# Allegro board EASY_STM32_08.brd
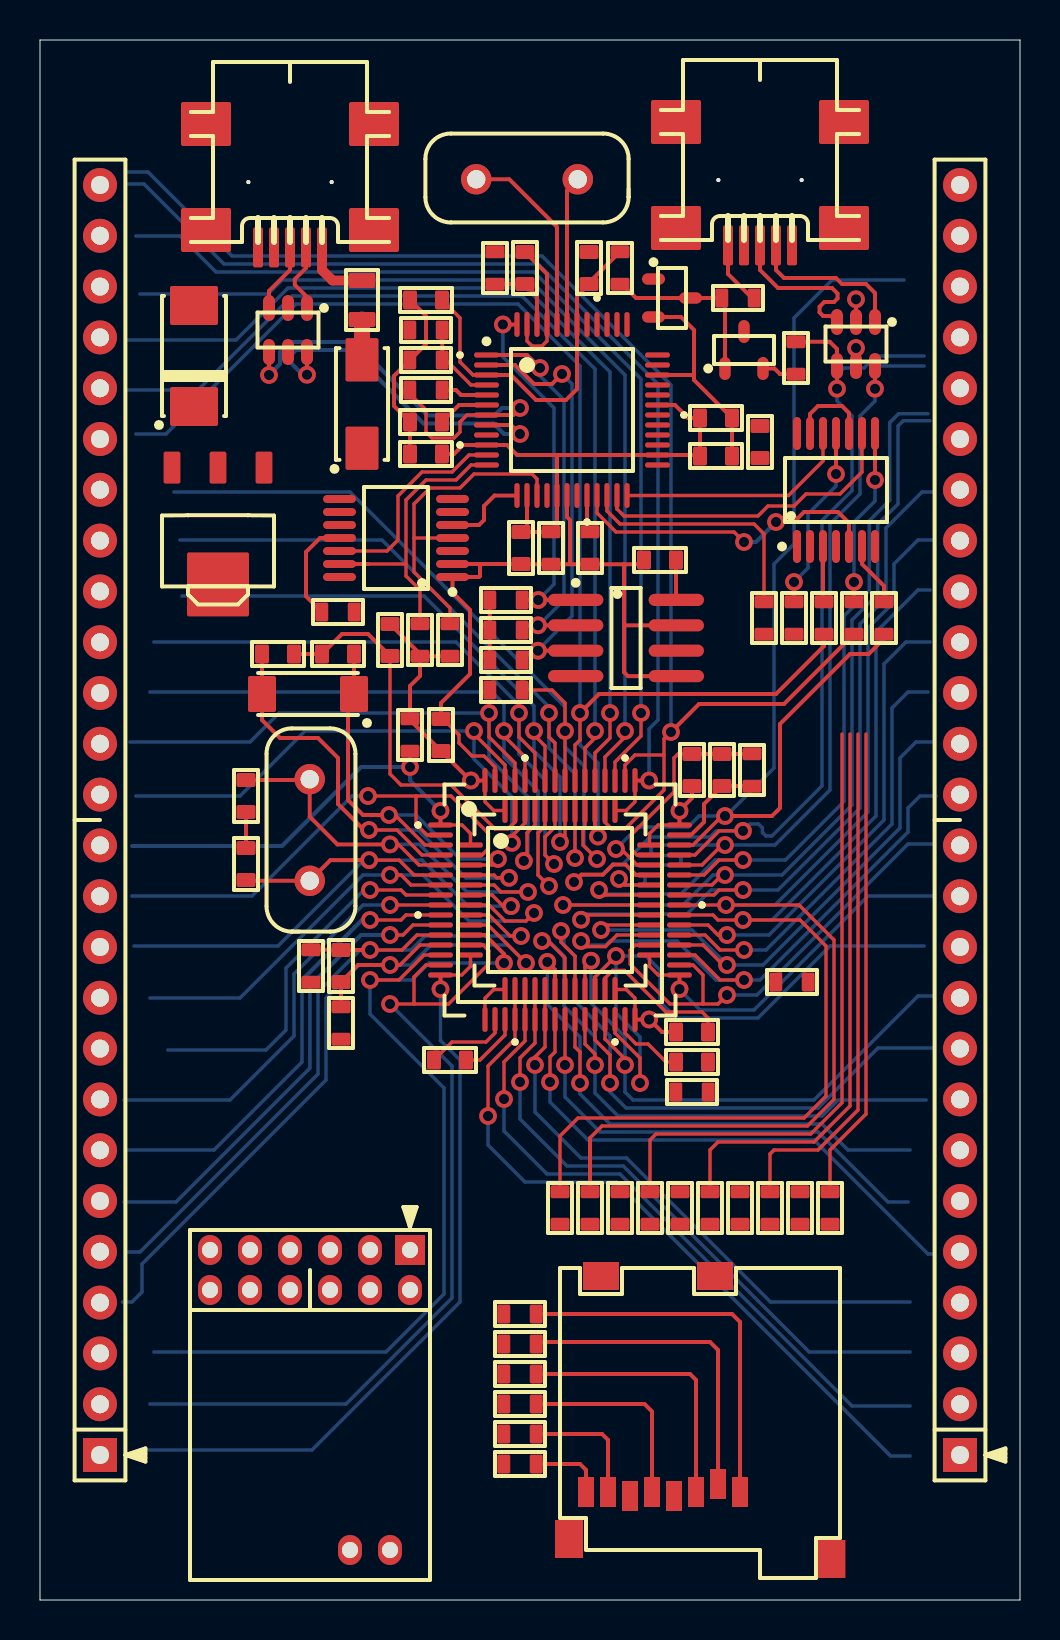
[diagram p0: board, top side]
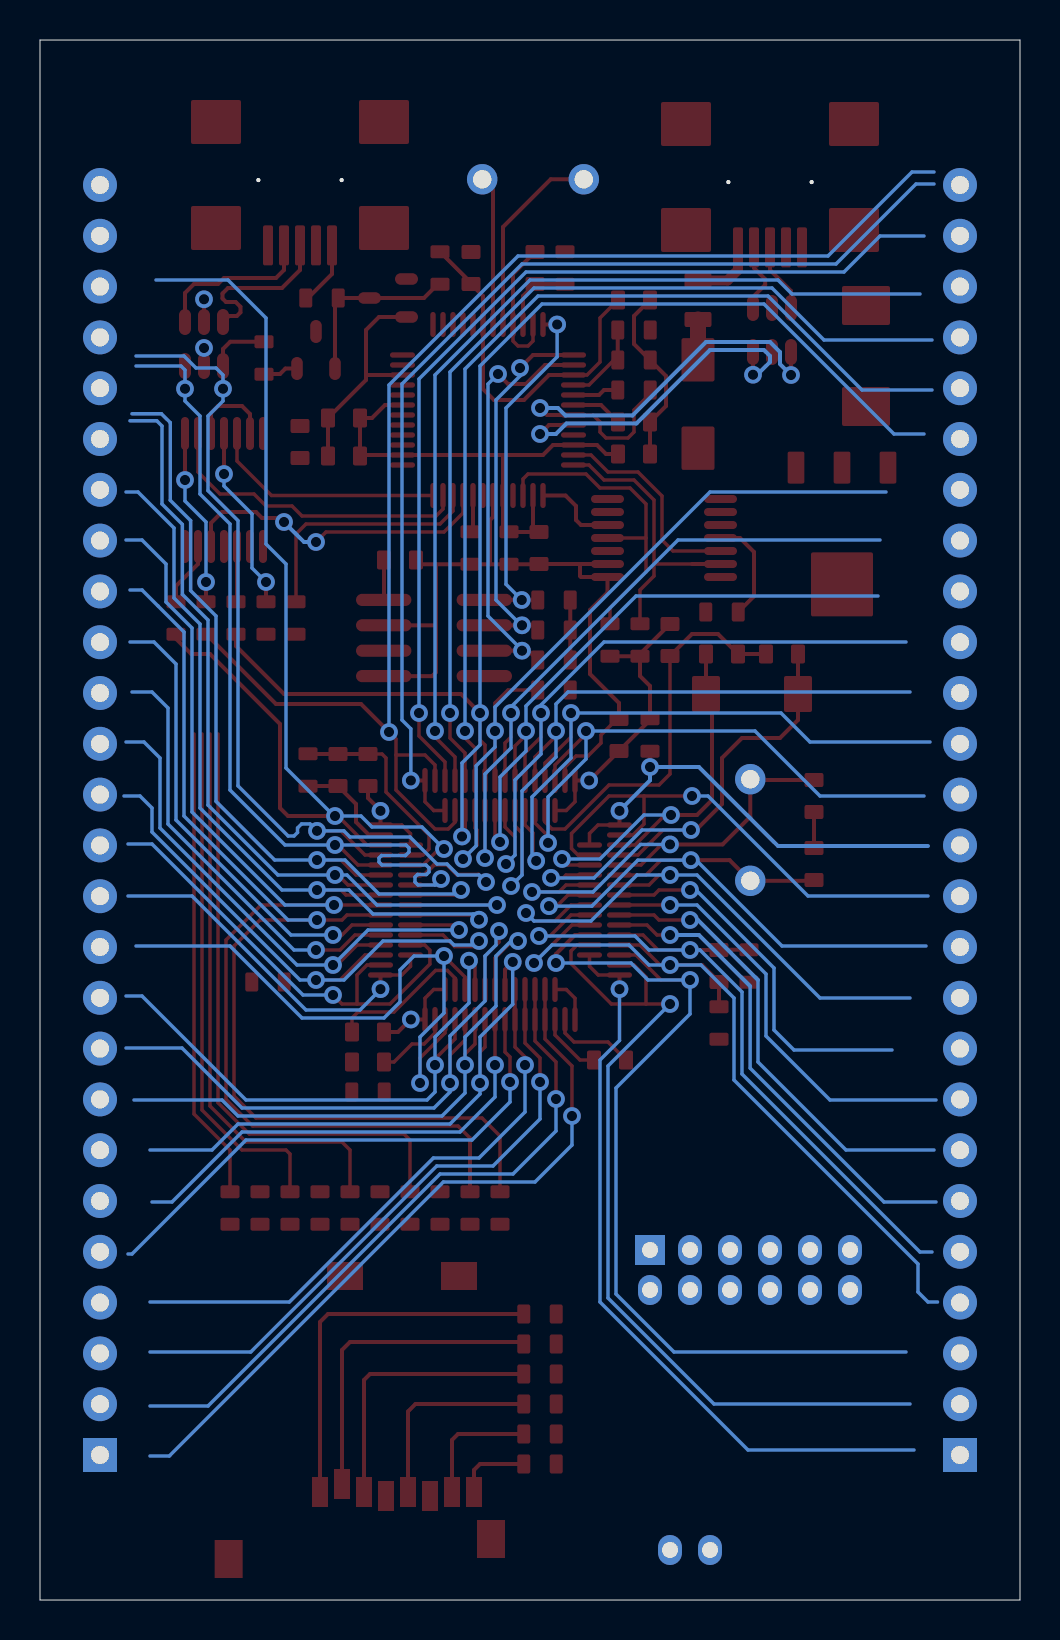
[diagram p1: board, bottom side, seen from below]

Outline 49 x 78 mm; copper layers: TOP, BOTTOM. Coordinates in mm from the lower left corner of the outline.
Outline path: 0,78 0,0 49,0 49,78 0,78

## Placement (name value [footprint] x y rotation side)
C1  22pF  [CAP0603_B]  10.3 40.2 270 top
C2  22p  [CAP0603_B]  10.3 36.8 90 top
C3  15p  [CAP0603_B]  11.9 47.3 0 top
C4  15p  [CAP0603_B]  14.9 47.3 180 top
C5  100n  [CAP0603_B]  15.05 31.7 90 top
C6  100n  [CAP0603_B]  32.6 28.4 0 top
C7  100n  [CAP0603_B]  32.6 41.5 90 top
C8  100n  [CAP0603_B]  20.05 43.25 90 top
C9  100n  [CAP0603_B]  20.5 27 180 top
C11  100n  [CAP0603_B]  19.3 65 180 top
C12  100n  [CAP0603_B]  27.45 66.6 90 top
C14  100n  [CAP0603_B]  19.3 57.3 180 top
C15  100n  [CAP0603_B]  24.05 52.6 270 top
C16  100n  [CAP0603_B]  33.8 57.2 0 top
C17  100n  [CAP0603_B]  33.8 59.1 0 top
C18  100n  [CAP0603_B]  24.25 66.6 90 top
C19  100n  [CAP0603_B]  19.3 58.9 180 top
C22  100n  [CAP0603_B]  31 52 180 top
C23  220uF  [CAP220UF]  7.7 62.2 90 top
C27  100n  [CAP0603_B]  32.6 26.9 0 top
C28  100n  [CAP0603_B]  34.1 41.5 90 top
C45  100nF  [CAP0603_B]  36 57.9 90 top
C46  100nF  [CAP0603_B]  17.5 48 270 top
D2  1N5819  [SS14]  16.1 59.8 90 top
J1  USB_MB  [HIROSE-US60-MB-5ST]  12.5 76.9 180 top
J2  USB_MB  [HIROSE-US60-MB-5ST]  36 77 180 top
J3  CON26  [HEADER26-1X26]  46 7.25 90 top
J4  CON26  [HEADER26-1X26]  3 7.25 90 top
L1  FB60R  [RES0805_B]  16.1 65 90 top
NOREF  -  [#2]  0 -2 0 top
NOREF#2  -  [#2]  50 0 90 top
Q1  C1815  [SOT-23]  35.2 62.5 0 top
Q2  C1815  [SOT-23]  31.6 65.1 270 top
R1  0R  [RES0603_B]  18.5 43.25 90 top
R2  0R  [RES0603_B]  15.05 28.85 270 top
R3  0R  [RES0603_B]  13.55 31.7 270 top
R4  470R  [RES0603_B]  22.75 66.6 270 top
R5  4K7  [RES0603_B]  19.3 63.5 0 top
R6  10K  [RES0603_B]  19.3 62 180 top
R7  10K  [RES0603_B]  27.5 52.6 270 top
R8  10K  [RES0603_B]  23.3 47 0 top
R9  10K  [RES0603_B]  23.3 48.5 0 top
R10  10K  [RES0603_B]  23.3 50 0 top
R13  1K5  [RES0603_B]  19.3 60.5 0 top
R14  100K  [RES0603_B]  25.55 52.6 270 top
R15  10K  [RES0603_B]  24 8.3 0 top
R16  10K  [RES0603_B]  24 11.3 0 top
R17  10K  [RES0603_B]  24 9.8 0 top
R18  10K  [RES0603_B]  24 12.8 0 top
R19  10K  [RES0603_B]  24 6.8 0 top
R20  10K  [RES0603_B]  24 14.3 0 top
R23  0R  [RES0603_B]  26 19.6 270 top
R24  0R  [RES0603_B]  33.5 19.6 270 top
R25  0R  [RES0603_B]  30.5 19.6 270 top
R26  0R  [RES0603_B]  36.5 19.6 270 top
R27  0R  [RES0603_B]  27.5 19.6 270 top
R28  0R  [RES0603_B]  39.5 19.6 270 top
R29  0R (DNP)  [RES0603_B]  29 19.6 90 top
R30  0R (DNP)  [RES0603_B]  35 19.6 90 top
R31  0R (DNP)  [RES0603_B]  32 19.6 90 top
R32  0R (DNP)  [RES0603_B]  38 19.6 90 top
R34  100K  [RES0603_B]  36.2 49.1 270 top
R35  100R  [RES0603_B]  39.2 49.1 270 top
R36  100R  [RES0603_B]  42.2 49.1 270 top
R37  100R  [RES0603_B]  40.7 49.1 270 top
R38  100R  [RES0603_B]  37.7 49.1 270 top
R39  100K  [RES0603_B]  19 48 90 top
R40  100K  [RES0603_B]  20.5 48 90 top
R41  100R  [RES0603_B]  23.3 45.5 0 top
R42  100R  [RES0603_B]  14.9 49.4 0 top
R43  0R  [RES0603_B]  32.6 25.4 0 top
R44  10K  [RES0603_B]  29 66.6 270 top
R45  36K  [RES0603_B]  34.9 65.1 0 top
R46  1K5  [RES0603_B]  37.8 62.1 90 top
R47  47K  [RES0603_B]  37.6 30.9 0 top
R48  0R  [RES0603_B]  35.6 41.5 90 top
REF  val  [unnamed]  18.5 17.5 180 top
U1  STM32F103RCT6  [LQFP64_MODIFIED]  26 35 0 top
U2  STM32F100  [LQFP48L_MODIFIED]  26 35 0 top
U3  FT2232D  [LQFP48L]  26.6 59.5 0 top
U4  AT93C46-10SI-2.7  [SOIC8S1JEDECM]  29.3 48.1 270 top
U5  74LVC125A  [TSOP65P640X120-14]  39.8 55.5 0 top
U6  74LVC125A  [TSOP65P640X120-14]  17.8 53.1 90 top
U7  LD1117-3V3  [SOT-223]  8.9 53.42 180 top
U10  MICRO_SD  [MICRO_SD_PUSH]  40 16.6 180 top
U11  USBLC6-2P6  [SOT23-6L]  40.8 62.8 180 top
U12  USBLC6-2P6  [SOT23-6L]  12.4 63.5 180 top
Y1  8M  [XTAL_DIP]  13.49 35.96 90 top
Y2  32.768KHz  [ABS10]  13.4 45.3 180 top
Y3  6M  [XTAL_DIP]  26.89 71.04 180 top

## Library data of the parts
C1-C9 C27 C28 = C1005_0: User Part Number: pn; Tolerance: RichardLC
C11 C12 C14-C19 C22 = CAP NP_0: User Part Number: pn; Tolerance: RichardLC
C23 = CAPACITOR POL: User Part Number: pn; Tolerance: RichardLC
C45 C46 = C1005_5: User Part Number: pn; Tolerance: RichardLC
D2 = DIODE SCHOTTKY_1: User Part Number: pn; Tolerance: RichardLC
J1 J2 = CON9_2: User Part Number: pn; Tolerance: RichardLC
J3 J4 = CON26: User Part Number: pn; Tolerance: RichardLC
L1 = INDUCTOR/SM_0: User Part Number: pn; Tolerance: RichardLC
Q1 Q2 = 2N3904_0: User Part Number: pn; Tolerance: RichardLC
R1-R10 R13-R20 R23-R32 R34-R48 = R_0: User Part Number: pn; Tolerance: RichardLC
REF = -: User Part Number: pn; Tolerance: RichardLC
U1 = STM32F103RCT6_2: User Part Number: pn; Tolerance: RichardLC
U2 = STM32F100_1: User Part Number: pn; Tolerance: RichardLC
U3 = FT2232D_0: User Part Number: pn; Tolerance: RichardLC
U4 = 93C46_2: User Part Number: pn; Tolerance: RichardLC
U5 U6 = 74HC125/LCC_0: User Part Number: pn; Tolerance: RichardLC
U7 = LD1117: User Part Number: pn; Tolerance: RichardLC
U10 = MOLEX_uSD_0: User Part Number: pn; Tolerance: RichardLC
U11 U12 = USBLC6-2P6: User Part Number: pn; Tolerance: RichardLC
Y1 Y3 = ZTB: Tolerance: ***; User Part Number: ***
Y2 = ZTA: User Part Number: pn; Tolerance: RichardLC

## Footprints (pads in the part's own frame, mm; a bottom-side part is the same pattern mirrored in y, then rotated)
ABS10
  custom 0.35x0.35 smd: 1(-2.3,0) 2(2.3,0)
CAP220UF
  custom 0.487x0.487 smd: 1(-2.525,0) 2(2.525,0)
CAP0603_B
  custom 0.175x0.175 smd: 1(-0.8,0) 2(0.8,0)
HEADER26-1X26
  rect 1.7x1.7 hole 0.9: 1(0,0)
  round 1.7 hole 0.9: 2(2.54,0) 3(5.08,0) 4(7.62,0) 5(10.16,0) 6(12.7,0) 7(15.24,0) 8(17.78,0) 9(20.32,0) 10(22.86,0) 11(25.4,0) 12(27.94,0) 13(30.48,0) 14(33.02,0) 15(35.56,0) 16(38.1,0) 17(40.64,0) 18(43.18,0) 19(45.72,0) 20(48.26,0) 21(50.8,0) 22(53.34,0) 23(55.88,0) 24(58.42,0) 25(60.96,0) 26(63.5,0)
HIROSE-US60-MB-5ST
  round 0.2 hole 0.9 unplated: (-2.083,6.005) (2.083,6.005)
  custom 0.125x0.125 smd: 1(-1.6,9.271) 2(-0.8,9.271) 3(0,9.271) 4(0.8,9.271) 5(1.6,9.271)
  custom 0.55x0.55 smd: 6(-4.2,3.1) 7(4.2,3.1) 8(-4.2,8.4) 9(4.2,8.4)
LQFP48L
  oval 1.25x0.27 smd: 1(-4.275,2.75) 2(-4.275,2.25) 3(-4.275,1.75) 4(-4.275,1.25) 5(-4.275,0.75) 6(-4.275,0.25) 7(-4.275,-0.25) 8(-4.275,-0.75) 9(-4.275,-1.25) 10(-4.275,-1.75) 11(-4.275,-2.25) 12(-4.275,-2.75) 25(4.275,-2.75) 26(4.275,-2.25) 27(4.275,-1.75) 28(4.275,-1.25) 29(4.275,-0.75) 30(4.275,-0.25) 31(4.275,0.25) 32(4.275,0.75) 33(4.275,1.25) 34(4.275,1.75) 35(4.275,2.25) 36(4.275,2.75)
  oval 0.27x1.25 smd: 13(-2.75,-4.275) 14(-2.25,-4.275) 15(-1.75,-4.275) 16(-1.25,-4.275) 17(-0.75,-4.275) 18(-0.25,-4.275) 19(0.25,-4.275) 20(0.75,-4.275) 21(1.25,-4.275) 22(1.75,-4.275) 23(2.25,-4.275) 24(2.75,-4.275) 37(2.75,4.275) 38(2.25,4.275) 39(1.75,4.275) 40(1.25,4.275) 41(0.75,4.275) 42(0.25,4.275) 43(-0.25,4.275) 44(-0.75,4.275) 45(-1.25,4.275) 46(-1.75,4.275) 47(-2.25,4.275) 48(-2.75,4.275)
LQFP48L_MODIFIED
  oval 1.25x0.27 smd: 1(-4.475,2.75) 2(-4.475,2.25) 3(-4.475,1.75) 4(-4.475,1.25) 5(-4.475,0.75) 6(-4.475,0.25) 7(-4.475,-0.25) 8(-4.475,-0.75) 9(-4.475,-1.25) 10(-4.475,-1.75) 11(-4.475,-2.25) 12(-4.475,-2.75) 25(4.475,-2.75) 26(4.475,-2.25) 27(4.475,-1.75) 28(4.475,-1.25) 29(4.475,-0.75) 30(4.475,-0.25) 31(4.475,0.25) 32(4.475,0.75) 33(4.475,1.25) 34(4.475,1.75) 35(4.475,2.25) 36(4.475,2.75)
  oval 0.27x1.25 smd: 13(-2.75,-4.475) 14(-2.25,-4.475) 15(-1.75,-4.475) 16(-1.25,-4.475) 17(-0.75,-4.475) 18(-0.25,-4.475) 19(0.25,-4.475) 20(0.75,-4.475) 21(1.25,-4.475) 22(1.75,-4.475) 23(2.25,-4.475) 24(2.75,-4.475) 37(2.75,4.475) 38(2.25,4.475) 39(1.75,4.475) 40(1.25,4.475) 41(0.75,4.475) 42(0.25,4.475) 43(-0.25,4.475) 44(-0.75,4.475) 45(-1.25,4.475) 46(-1.75,4.475) 47(-2.25,4.475) 48(-2.75,4.475)
LQFP64_MODIFIED
  oval 1.25x0.27 smd: 1(-5.975,3.75) 2(-5.975,3.25) 3(-5.975,2.75) 4(-5.975,2.25) 5(-5.975,1.75) 6(-5.975,1.25) 7(-5.975,0.75) 8(-5.975,0.25) 9(-5.975,-0.25) 10(-5.975,-0.75) 11(-5.975,-1.25) 12(-5.975,-1.75) 13(-5.975,-2.25) 14(-5.975,-2.75) 15(-5.975,-3.25) 16(-5.975,-3.75) 33(5.975,-3.75) 34(5.975,-3.25) 35(5.975,-2.75) 36(5.975,-2.25) 37(5.975,-1.75) 38(5.975,-1.25) 39(5.975,-0.75) 40(5.975,-0.25) 41(5.975,0.25) 42(5.975,0.75) 43(5.975,1.25) 44(5.975,1.75) 45(5.975,2.25) 46(5.975,2.75) 47(5.975,3.25) 48(5.975,3.75)
  oval 0.27x1.25 smd: 17(-3.75,-5.975) 18(-3.25,-5.975) 19(-2.75,-5.975) 20(-2.25,-5.975) 21(-1.75,-5.975) 22(-1.25,-5.975) 23(-0.75,-5.975) 24(-0.25,-5.975) 25(0.25,-5.975) 26(0.75,-5.975) 27(1.25,-5.975) 28(1.75,-5.975) 29(2.25,-5.975) 30(2.75,-5.975) 31(3.25,-5.975) 32(3.75,-5.975) 49(3.75,5.975) 50(3.25,5.975) 51(2.75,5.975) 52(2.25,5.975) 53(1.75,5.975) 54(1.25,5.975) 55(0.75,5.975) 56(0.25,5.975) 57(-0.25,5.975) 58(-0.75,5.975) 59(-1.25,5.975) 60(-1.75,5.975) 61(-2.25,5.975) 62(-2.75,5.975) 63(-3.25,5.975) 64(-3.75,5.975)
MICRO_SD_PUSH
  rect 0.8x1.5 smd: 1(5,11.2) 2(6.1,10.8) 3(7.2,11.2) 4(8.3,11.4) 5(9.4,11.2) 6(10.5,11.4) 7(11.6,11.2) 8(12.7,11.2)
  rect 1.4x1.9 smd: G1(0.43,14.55) G2(13.55,13.55)
  rect 1.8x1.4 smd: S1(6.25,0.4) S2(11.95,0.4)
RES0603_B
  custom 0.163x0.163 smd: 1(-0.812,0) 2(0.812,0)
RES0805_B
  custom 0.188x0.188 smd: 1(-0.975,0) 2(0.975,0)
SOIC8S1JEDECM
  oval 0.61x2.77 smd: 1(-1.905,-2.515) 2(-0.635,-2.515) 3(0.635,-2.515) 4(1.905,-2.515) 5(1.905,2.515) 6(0.635,2.515) 7(-0.635,2.515) 8(-1.905,2.515)
SOT23-6L
  oval 0.6x1.3 smd: 1(-0.95,-1.1) 2(0,-1.1) 3(0.95,-1.1) 4(0.95,1.1) 5(0,1.1) 6(-0.95,1.1)
SOT-23
  oval 0.58x1.15 smd: 1(-0.95,-0.925) 2(0.95,-0.925) 3(0,0.925)
SOT-223
  custom 0.21x0.21 smd: 1(-2.3,-3.195) 2(0,-3.195) 3(2.3,-3.195)
  custom 0.775x0.775 smd: 4(0,2.645)
SS14
  custom 0.412x0.412 smd: A(2.21,0) C(-2.21,0)
TSOP65P640X120-14
  oval 0.4x1.65 smd: 1(-1.95,-2.825) 2(-1.3,-2.825) 3(-0.65,-2.825) 4(0,-2.825) 5(0.65,-2.825) 6(1.3,-2.825) 7(1.95,-2.825) 8(1.95,2.825) 9(1.3,2.825) 10(0.65,2.825) 11(0,2.825) 12(-0.65,2.825) 13(-1.3,2.825) 14(-1.95,2.825)
unnamed
  rect 1.5x1.5 hole 0.8: 1(0,0)
  oval 1.194x1.499 hole 0.8: 2(0,2) 3(2,0) 4(2,2) 5(4,0) 6(4,2) 7(6,0) 8(6,2) 9(8,0) 10(8,2) 11(10,0) 12(10,2) 13(1,15) 14(3,15)
XTAL_DIP
  round 1.524 hole 0.914: 1(0,0) 2(5.08,0)

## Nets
+3V3: C6.1 C7.1 C8.1 C9.1 C14.1 C15.1 C16.1 C17.1 C45.1 C46.1 Q1.3(C) R1.2 R2.2 R14.1 R15.1 R16.1 R17.1 R18.1 R19.1 R20.1 R39.1 R40.1 R47.1 U1.19(VDD_4) U1.32(VDD_1) U1.48(VDD_2) U1.64(VDD_3) U2.24(VDD_1) U2.36(VDD_2) U2.48(VDD_3) U3.10(SI/WUA) U3.14(VCCIOA) U3.17(ADBUS6) U3.26(SI/WUB) U3.31(VCCIOB) U5.14(VCC) U6.14(VCC) U7.2(VOUT) U7.4(SH) U10.4(VDD)
+5V: C11.1 C12.1 C22.1 C23.1 D2.C R4.1 R8.1 R9.1 R10.1 R44.1 U3.3(VCC1) U3.42(VCC2) U4.8(VCC) U7.3(VIN) U11.5(VBUS) U12.5(VBUS)
GND: C1.2 C2.2 C3.2 C4.2 C6.2 C7.2 C8.2 C9.2 C11.2 C12.2 C14.2 C15.2 C16.2 C17.2 C18.2 C19.2 C22.2 C23.2 C27.2 C28.2 C45.2 C46.2 J1.5(GND) J1.6(SH1) J1.7(SH2) J1.8(SH3) J1.9(SH4) J2.5(GND) J2.6(SH1) J2.7(SH2) J2.8(SH3) J2.9(SH4) Q2.2(E) R3.2 R6.2 R7.2 R14.2 R34.2 R43.2 R45.2 R48.2 U1.18(VSS_4) U1.63(VSS_3) U2.23(VSS_1) U2.35(VSS_2) U2.47(VSS_3) U3.9(GND1) U3.18(GND2) U3.25(GND3) U3.34(GND4) U3.45(AGND) U3.47(TEST) U4.5(GND) U4.7(NC) U5.7(GND) U6.1(O\E\1\) U6.2(A1) U6.7(GND) U6.9(A3) U6.10(O\E\3\) U7.1(GND) U10.6(VSS) U11.2(GND) U12.2(GND)
VBAT: R1.1 U1.1(VBAT) U2.1(VBAT)
VDDA: C5.1 R2.1 U1.13(VDDA) U2.9(VDDA)
VSSA: C5.2 R3.1 U1.12(VSSA) U2.8(VSSA)
BOOT0: U1.60(BOOT0) U2.44(BOOT0)
EECK: R9.2 U3.1(EESK) U4.2(CLK)
EECS: R10.2 U3.48(EECS) U4.1(CS)
EEDA: R8.2 U3.2(EEDATA) U4.3(DI)
JT_SRSTN: U3.16(ADBUS7)
JTG_SELN: U5.1(O\E\1\) U5.4(O\E\2\) U5.10(O\E\3\) U5.13(O\E\4\)
NRST: R42.2 U1.7(NRST) U2.7(NRST)
OSC32_IN: C4.1 U1.3(PC14/OSC32_IN) U2.3(PC14/OSC32_IN) Y2.1
OSC32_OUT: C3.1 U1.4(PC15/OSC32/OUT) U2.4(PC15/OSC32_OUT) Y2.2
OSC_IN: C1.1 U1.5(PD0/OSC_IN) U2.5(PD0/OSC_IN) Y1.2
OSC_OUT: C2.1 U1.6(PD1/OSC_OUT) U2.6(PD1/OSC_OUT) Y1.1
PA0: U1.14(PA0-WKUP) U2.10(PA0/WKUP)
PA1: U1.15(PA1) U2.11(PA1)
PA2: U1.16(PA2) U2.12(PA2)
PA3: U1.17(PA3) U2.13(PA3)
PA4: R32.2 U1.20(PA4) U2.14(PA4)
PA5: R31.2 U1.21(PA5) U2.15(PA5)
PA6: R29.2 U1.22(PA6) U2.16(PA6)
PA7: R30.2 U1.23(PA7) U2.17(PA7)
PA8: U1.41(PA8) U2.29(PA8)
PA9: U1.42(PA9) U2.30(PA9)
PA10: U1.43(PA10) U2.31(PA10)
PA11: U1.44(PA11) U2.32(PA11) U11.6(IO1_2)
PA12: R46.2 U1.45(PA12) U2.33(PA12) U11.4(IO2_2)
PA13: R36.2 U1.46(PA13) U2.34(PA13)
PA14: R38.2 U1.49(PA14) U2.37(PA14)
PA15: R37.2 U1.50(PA15) U2.38(PA15)
PB0: U1.26(PB0) U2.18(PB0)
PB1: U1.27(PB1) U2.19(PB1)
PB2: U1.28(PB2/BOOT1) U2.20(PB2)
PB3: R35.2 U1.55(PB3) U2.39(PB3)
PB4: R41.2 U1.56(PB4) U2.40(PB4)
PB5: U1.57(PB5) U2.41(PB5)
PB6: U1.58(PB6) U2.42(PB6)
PB7: U1.59(PB7) U2.43(PB7)
PB8: U1.61(PB8) U2.45(PB8)
PB9: U1.62(PB9) U2.46(PB9)
PB10: U1.29(PB10) U2.21(PB10)
PB11: U1.30(PB11) U2.22(PB11)
PB12: U1.33(PB12) U2.25(PB12)
PB13: U1.34(PB13) U2.26(PB13)
PB14: Q2.1(B) R47.2 U1.35(PB14) U2.27(PB14)
PB15: U1.36(PB15) U2.28(PB15)
PC0: U1.8(PC0)
PC1: U1.9(PC1)
PC2: U1.10(PC2)
PC3: U1.11(PC3)
PC4: U1.24(PC4)
PC5: U1.25(PC5)
PC6: U1.37(PC6)
PC7: U1.38(PC7)
PC8: R23.1 U1.39(PC8)
PC9: R27.1 U1.40(PC9)
PC10: R28.1 U1.51(PC10)
PC11: R26.1 U1.52(PC11)
PC12: R25.1 U1.53(PC12)
PC13: U1.2(PC13/TAMPER/RTC) U2.2(PC13/TAMPER/RTC)
PD2: R24.1 U1.54(PD2)
RXD: U3.39(BDBUS1)
SRST: U3.11(ACBUS3) U6.12(A4)
SRST_OE: R39.2 U3.12(ACBUS2) U6.13(O\E\4\)
TRST: U3.13(ACBUS1) U6.5(A2)
TRST_OE: R40.2 U3.15(ACBUS0) U6.4(O\E\2\)
TXD: U3.40(BDBUS0)
USB_CLK: U3.24(ADBUS0) U5.12(A4)
USB_TDI: U3.23(ADBUS1) U5.9(A3)
USB_TDO: R34.1 U3.22(ADBUS2) U5.2(A1)
USB_TMS: U3.21(ADBUS3) U5.5(A2)
N50123: R13.1 U3.7(USBDP) U12.4(IO2_2)
N50127: C18.1 R4.2 U3.46(AVCC)
N50535: R7.1 U3.20(ADBUS4)
N50793: U3.43(XTIN) Y3.1
N50801: U3.44(XTOUT) Y3.2
N51029: D2.A L1.1 R5.1
N51243: J1.1(VBUS) L1.2
N51319: R13.2 U3.5(R\S\T\O\U\T\)
N51343: U3.8(USBDM) U12.6(IO1_2)
N51347: R5.2 R6.1 U3.4(R\E\S\E\T\)
N51363: C19.1 U3.6(3V3OUT)
N51511: U4.4(DO)
N70187: R15.2 R23.2 R29.1 U10.7(DAT0/DO)
N70219: R17.2 R25.2 R31.1 U10.5(CLK)
N70227: R18.2 R26.2 R32.1 U10.2(CD/C\S\/DAT3)
N70305: U10.S2
N70345: U10.G2
N70603: R19.2 R27.2 U10.8(DAT1/RSV)
N14914218: R16.2 R24.2 R30.1 U10.3(CMD/DI)
N14919452: R35.1 U5.3(Y1)
N14919456: R36.1 U5.6(Y2)
N14919460: R37.1 U5.8(Y3)
N14919464: R38.1 U5.11(Y4)
N14919761: R20.2 R28.2 U10.1(DAT2/NC)
N14928576: R41.1 U6.6(Y2)
N14928580: R42.1 U6.11(Y4)
N14948550: J2.1(VBUS)
N14948554: J2.2(DM) U11.1(IO1_1)
N14948558: J2.3(DP) U11.3(IO2_1)
N14952468: Q1.2(E) R46.1
N14953185: Q1.1(B) Q2.3(C) R44.2 R45.1
N14959571: J1.3(DP) U12.3(IO2_1)
N14961045: J1.2(DM) U12.1(IO1_1)
N14964930: C27.1 R43.1 U1.31(VSS_1)
N14964937: C28.1 R48.1 U1.47(VSS_2)

Pads without a net: J1 4; J2 4; J3 1 2 3 4 5 6 7 8 9 10 11 12 13 14 15 16 17 18 19 20 21 22 23 24 25 26; J4 1 2 3 4 5 6 7 8 9 10 11 12 13 14 15 16 17 18 19 20 21 22 23 24 25 26; REF 1 2 3 4 5 6 7 8 9 10 11 12 13 14; U3 19 27 28 29 30 32 33 35 36 37 38 41; U4 6; U6 3 8; U10 G1 S1

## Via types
v1: diameter 0.889, hole 0.508, TOP to BOTTOM, 108 vias

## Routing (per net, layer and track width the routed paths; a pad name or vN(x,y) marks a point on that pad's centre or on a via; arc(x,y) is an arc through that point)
+3V3: length 51.7
  TOP w0.175: U1.64 22.25,39.91 22.69,39.48 U2.48 ; U2.24 29.32,30.52 29.57,30.27 29.75,30.09 U1.32 ; C9.1 22,27 23.25,28.25 U1.19 ; U2.36 30.48,38.31 30.91,38.75 U1.48
  TOP w0.2: U3.31 31.75,59.75 32.4,59.1 C17.1 C16.1 32.95,57.25 U3.26 25.8,57.25 ; U1.32 v1(30.46,29.02) 30.48,29.02 31.1,28.4 C6.1 ; 25.8,57.25 23.85,57.25 23.35,57.75 U3.10 21.15,57.75 20.7,57.3 C14.1 ; 25.8,57.25 25.85,57.2 U3.17 25.85,53.71 R14.1 25.54,53.4 C15.1 24.35,53.7 U3.14 ; R39.1 19,47.3 C46.1 ; R39.1 R40.1 ; R39.1 19,46.2 18.5,45.7 R1.2 18.5,44 C8.1 21.52,40.98 v1(21.54,40.98) U1.64 ; C7.1 32.6,40.1 31.98,39.48 v1(31.98,39.46) U1.48
+5V: length 24
  TOP w0.175: C11.1 21,64.1 21,61.9 21.65,61.25 U3.3
  TOP w0.2: 31.82,50.01 31.8,50.02 C22.1 ; U11.5 v1(40.8,62.6) ; R44.1 27.45,65.86 C12.1 26.85,65.2 U3.42 26.85,60.55 26.3,60 24.8,60 23.55,61.25 U3.3 ; R8.1 R9.1 R10.1
GND: length 113.9
  TOP w0.175: U1.63 22.75,41.65 22.2,42.2 21.6,42.2 20.95,42.85 20.95,43.25 20.15,44.05 C8.2 ; U2.47 23.75,38.9 23.4,38.55 22.75,38.55 20.55,40.75 18.05,40.75 17.5,41.3 C46.2 ; C7.2 31.9,42.3 31.7,42.1 31.7,40.4 29.55,38.25 29.55,37.55 29.85,37.25 U2.35 ; C9.2 20.6,27.9 22.3,27.9 22.75,28.35 U1.18 ; U3.47 24.35,62.95 24.6,62.7 25.1,62.7 25.35,62.95 U3.45 ; C6.2 33.4,29.1 33.1,29.4 31.3,29.4 29.22,31.48 28.63,31.48 28.25,31.09 U2.23
  TOP w0.2: C3.2 C4.2 15.1,48.3 16.4,48.3 C46.2 ; C8.2 20.05,44.85 21.5,46.3 21.5,49.5 20.62,50.38 20.62,51.15 21.95,51.15 22,51.2 22,51.8 ; C2.2 C1.2 ; U11.2 v1(40.8,65.04) ; C14.2 C19.2 17.7,59.7 17.7,61.2 18.49,61.99 R6.2 18.5,62 19.3,62.8 19.3,64.2 C11.2 ; 29.2,51.79 R7.2 26.5,51.79 ; 29.2,51.79 29.2,48.7 ; 29.2,51.79 29.99,51.79 C22.2 ; R48.2 35.59,42.3 C28.2 C7.2 ; Q2.2 32.05,64.15 32.7,63.5 32.7,61.3 ; U3.18 26.35,54.15 26.5,54 26.5,51.79 ; 32.7,61.3 32.65,61.25 U3.34 ; 32.7,61.3 32.7,61 C17.2 C16.2 ; 31.82,46.2 29.39,46.2 29.2,46.39 29.2,48.7 ; 29.2,48.7 29.23,48.73 31.82,48.73 ; 22,51.8 C15.2 24.06,51.79 R14.2 26.5,51.79 ; 22,51.8 20.62,51.8 ; C18.2 25.35,66.3 U3.45 ; R45.2 35.6,65.1 34.4,66.3 J2.5
VBAT: length 22.1
  TOP w0.175: U1.1 21.1,38.75 21.52,38.33 U2.1
  TOP w0.2: R1.1 v1(18.5,41.65) ; U1.1 v1(20.02,39.46)
  BOTTOM w0.2: v1(20.02,39.46) 18.5,40.98 v1(18.5,41.65) 16.05,41.65 12.1,37.7 4.6,37.7
VDDA: length 41.7
  TOP w0.175: v1(24.3,31.85) 22.4,33.75 U2.9 ; U1.13 19,32.75 18,31.75 v1(17.5,31.75)
  TOP w0.2: R2.1 C5.1 15.9,31.75 v1(17.5,31.75)
  BOTTOM w0.175: 4.12,14.9 4.6,14.9 5.1,15.4 5.1,16.8 14.3,26 14.3,30.1 15.95,31.75 v1(17.5,31.75) 18.55,31.75 19.55,32.75 23.4,32.75 v1(24.3,31.85)
VSSA: length 38.3
  TOP w0.175: v1(16.5,32.5) 18.1,32.5 18.85,33.25 U1.12 ; U2.8 22.45,34.25 23.5,33.2 v1(24.05,33.2)
  TOP w0.2: R3.1 15.04,32.51 C5.2 v1(16.5,32.5)
  BOTTOM w0.175: 4.4,17.4 5,17.4 13.9,26.3 13.9,30.4 16,32.5 v1(16.5,32.5) 18.55,32.5 19.25,33.2 v1(24.05,33.2)
BOOT0: length 35
  TOP w0.175: v1(23.2,43.45) 23.2,43.2 24.25,42.15 U1.60 ; U2.44 25.25,38.7 24.9,38.35 24.9,36.25 v1(25.45,35.7)
  BOTTOM w0.175: v1(25.45,35.7) 24.9,36.25 24.9,40.45 23.2,42.15 v1(23.2,43.45) 23.2,44.8 22.6,45.4 5.5,45.4
EECK: length 19.6
  TOP w0.2: U3.1 24.35,62.25 v1(25,61.6) ; U4.2 v1(24.9,48.73) 24.35,48.73 R9.2
  BOTTOM w0.175: v1(25,61.6) 25,61.2 26.2,60 26.2,50 24.93,48.73 v1(24.9,48.73)
EECS: length 19.3
  TOP w0.2: v1(24.91,50) R10.2 24.12,50.01 U4.1 ; U3.48 v1(23.14,63.77)
  BOTTOM w0.175: v1(24.91,50) 25.7,50.79 25.7,59.6 23.14,62.16 v1(23.14,63.77)
EEDA: length 22
  TOP w0.2: U3.2 23.75,61.75 24.7,60.8 25.6,60.8 v1(26.1,61.3) ; R8.2 24.58,47.47 v1(24.9,47.47) U4.3
  BOTTOM w0.175: v1(24.9,47.47) 24.9,47.5 26.6,49.2 26.6,60.8 v1(26.1,61.3)
JTG_SELN: length 4.3
  TOP w0.2: U5.10 40.45,59.35 40.1,59.7 38.9,59.7 38.5,59.3 U5.13
NRST: length 29.3
  TOP w0.175: v1(17.5,36.25) 18.05,36.25 18.55,35.75 U1.7 ; U2.7 22.45,34.75 23.25,33.95 24.3,33.95 v1(24.7,34.35)
  BOTTOM w0.175: v1(24.7,34.35) 24.3,33.95 21.45,33.95 19.15,36.25 v1(17.5,36.25) 16.15,36.25 10,30.1 5.5,30.1
OSC32_IN: length 20.8
  TOP w0.175: v1(17.45,39.25) 17.75,39.25 19.25,37.75 U1.3 ; v1(22.9,37.05) 22.6,36.75 U2.3
  TOP w0.2: C4.1 Y2.1 15.4,45 15.4,40 16.15,39.25 v1(17.45,39.25)
  BOTTOM w0.175: v1(22.9,37.05) 21,37.05 18.8,39.25 v1(17.45,39.25)
OSC32_OUT: length 26.3
  TOP w0.175: v1(23.45,36.11) 22.84,36.11 22.7,36.25 U2.4 ; U1.4 19.1,37.25 17.85,38.5 v1(16.45,38.5)
  TOP w0.2: C3.1 Y2.2 11.1,44 12,43.1 13.9,43.1 14.9,42.1 14.9,39.8 16.2,38.5 v1(16.45,38.5)
  BOTTOM w0.175: v1(23.45,36.11) 23.44,36.1 21.3,36.1 18.9,38.5 v1(16.45,38.5)
OSC_IN: length 23.5
  TOP w0.175: v1(17.5,37.78) 17.92,37.78 18.95,36.75 U1.5 ; v1(24.4,35.4) 23.05,35.4 22.7,35.75 U2.5
  TOP w0.2: v1(17.5,37.78) 14.87,37.78 13.49,39.16 Y1.2 13.45,41 C1.1
  BOTTOM w0.175: v1(17.5,37.78) 18.97,37.78 21.35,35.4 v1(24.4,35.4)
OSC_OUT: length 34.3
  TOP w0.175: v1(23.55,34.69) 23.16,34.69 22.6,35.25 U2.6 ; U1.6 18.7,36.25 17.96,36.99 v1(16.46,36.99)
  TOP w0.2: C2.1 10.34,35.96 Y1.1 14.52,36.99 v1(16.46,36.99)
  BOTTOM w0.175: v1(23.55,34.69) 21.41,34.69 19.11,36.99 v1(16.46,36.99) 16.19,36.99 11.9,32.7 4.7,32.7
PA0: length 46.5
  TOP w0.175: v1(16.5,31) 17.95,31 19.2,32.25 U1.14
  TOP w0.2: v1(23.2,31.85) 23.2,32.3 22.25,33.25 U2.10
  BOTTOM w0.175: v1(23.2,31.85) 19.45,31.85 18.6,31 v1(16.5,31) 16.5,29.3 20.2,25.6 20.2,15.3 17.3,12.4 5.7,12.4
PA1: length 43.7
  TOP w0.175: 18.7,29.8 20.43,29.8 22.45,31.82 22.45,32.45 22.15,32.75 U2.11 ; 18.7,29.8 18.7,31.15 19.3,31.75 U1.15 ; 18.7,29.8 v1(17.5,29.8)
  BOTTOM w0.175: v1(17.5,29.8) 20.6,26.7 20.6,15.1 15.3,9.8 5.5,9.8
PA2: length 37.8
  TOP w0.175: U1.16 21.09,31.25 21.52,31.68 U2.12
  TOP w0.2: U1.16 v1(20.02,30.54)
  BOTTOM w0.175: 5.3,7.5 13.6,7.5 21,14.9 21,27 20.02,27.98 v1(20.02,30.54)
PA3: length 2.2
  TOP w0.175: U1.17 22.25,30.09 22.68,30.52 U2.13
PA4: length 36.1
  TOP w0.175: 23.75,30.73 U2.14 U1.20 23.75,28.05 22.4,26.7 v1(22.4,24.2)
  BOTTOM w0.175: 43.5,7.2 42.53,7.2 28.83,20.9 24.25,20.9 22.4,22.75 v1(22.4,24.2)
PA5: length 33.7
  TOP w0.175: v1(23.2,25.05) 23.2,26.9 24.25,27.95 U1.21 U2.15 24.25,30.73
  BOTTOM w0.175: 43.5,9.7 40.6,9.7 29,21.3 25.35,21.3 23.2,23.45 v1(23.2,25.05)
PA6: length 31.3
  TOP w0.175: v1(24,25.9) 24,27.1 24.75,27.85 U1.22 U2.16 24.75,30.73
  BOTTOM w0.175: 43.5,12.4 38.46,12.4 29.16,21.7 26.35,21.7 24,24.05 v1(24,25.9)
PA7: length 29.2
  TOP w0.175: 25.25,30.73 U2.17 U1.23 25.25,27.65 24.75,27.15 v1(24.75,26.75)
  BOTTOM w0.175: v1(24.75,26.75) 24.75,24.4 27.05,22.1 29.33,22.1 36.53,14.9 43.5,14.9
PA8: length 40.7
  TOP w0.175: U1.41 33.7,35.25 33.95,35.5 v1(35.15,35.5) ; U2.29 27.3,34.25 27.06,34.01 v1(27.05,34.01)
  BOTTOM w0.175: v1(27.05,34.01) 27.34,34.3 32.35,34.3 33.55,35.5 v1(35.15,35.5) 36.9,35.5 41,39.6 41,48.8 42.3,50.1 42.3,53.6 44.1,55.4 44.7,55.4
PA9: length 44.9
  TOP w0.175: v1(34.25,36.25) 34.1,36.25 33.6,35.75 U1.42 ; v1(26.15,34.75) U2.30
  BOTTOM w0.175: v1(26.15,34.75) 32.15,34.75 33.65,36.25 v1(34.25,36.25) 37.1,36.25 40.6,39.75 40.6,49 41.88,50.28 41.88,53.78 42.9,54.8 42.9,58.7 43.16,58.96 44.5,58.96
PA10: length 42.3
  TOP w0.175: v1(35.15,37) 33.95,37 33.2,36.25 U1.43 ; U2.31 28.3,35.25 28.05,35.5 v1(27.95,35.5)
  BOTTOM w0.175: v1(27.95,35.5) 28.15,35.3 32.05,35.3 33.75,37 v1(35.15,37) 37.27,37 40.2,39.93 40.2,49.2 41.47,50.47 41.47,53.97 42.49,54.99 42.49,58.87 42.93,59.31 44.4,59.31
PA11: length 47.5
  TOP w0.175: v1(34.25,37.75) 34.1,37.75 33.1,36.75 U1.44 ; U2.32 29.25,35.75 v1(28.95,36.05)
  TOP w0.2: U11.6 v1(41.75,60.56)
  BOTTOM w0.175: 44.2,61.7 41.95,61.7 41.75,61.5 v1(41.75,60.56) 41.75,59.95 41,59.2 41,55.3 39.5,53.8 39.5,40.5 36.75,37.75 v1(34.25,37.75) 30.7,37.75 30.55,37.6 30.55,37.4 30.73,37.23 31.93,37.23 32.05,37.1 32.05,36.9 31.9,36.75 29.7,36.75 29.55,36.6 29.55,36.4 29.68,36.27 30.12,36.27 30.25,36.15 30.25,35.9 30.1,35.75 29.25,35.75 v1(28.95,36.05)
PA12: length 53.5
  TOP w0.175: v1(35.15,38.46) 33.96,38.46 32.75,37.25 U1.45
  TOP w0.2: U2.33 29.8,36.25 29.28,36.77 28.65,36.77 28.15,36.27 27.07,36.27 v1(26.7,35.9) ; R46.2 39.49,62.91 39.85,62.55 U11.4 v1(39.85,60.56)
  BOTTOM w0.175: v1(26.7,35.9) 27.05,36.25 28.1,36.25 28.65,36.8 29.15,36.8 30.5,38.15 33.5,38.15 33.81,38.46 v1(35.15,38.46) 35.49,38.8 35.92,38.8 36.12,38.6 36.12,38.38 36.3,38.2 36.59,38.2 39.1,40.71 39.1,53.97 40.6,55.47 40.6,59.2 39.85,59.95 v1(39.85,60.56) 39.85,61.25 40.2,61.6 41.2,61.6 41.8,62.2 44.2,62.2
PA13: length 58
  TOP w0.175: v1(28.8,37.55) 29.05,37.55 29.85,36.75 U2.34 ; v1(34.25,39.2) 34.1,39.2 32.65,37.75 U1.46
  TOP w0.2: v1(34.25,39.2) 36.6,39.2 37,39.6 37,43.8 40.5,47.3 41.44,47.3 42.2,48.06 R36.2
  BOTTOM w0.175: v1(28.8,37.55) 29.9,38.65 32.4,38.65 32.95,39.2 v1(34.25,39.2) 34.3,39.2 36.7,41.6 36.7,51.8 37.7,52.8 37.7,64.1 39.6,66 43.2,66
PA14: length 53.7
  TOP w0.175: U1.49 29.75,39.91 29.32,39.48 U2.37
  TOP w0.2: U1.49 v1(30.46,40.98)
  BOTTOM w0.175: v1(30.46,40.98) 30.46,43.56 30.9,44 30.9,60.8 24.9,66.8 9.2,66.8 5.2,70.8 4.3,70.8
PA15: length 70.6
  TOP w0.175: v1(31.55,43.4) 31.2,43.05 31.2,42.25 ; 31.2,42.25 31.2,40.5 29.25,38.55 28.59,38.55 28.25,38.89 U2.38 ; 31.2,42.25 29.75,42.25 29.25,41.75 U1.50
  TOP w0.2: v1(31.55,43.4) 32.95,44.8 37.2,44.8 40.69,48.29 R37.2
  BOTTOM w0.175: 4.3,71.4 5.4,71.4 9.6,67.2 25.1,67.2 31.55,60.75 v1(31.55,43.4)
PB0: length 29.8
  TOP w0.175: v1(27,25.85) 27,27.4 26.75,27.65 U1.26
  TOP w0.2: v1(25.36,31.9) 25.75,31.52 U2.18
  BOTTOM w0.175: v1(25.36,31.9) 25.36,29.79 27,28.15 v1(27,25.85) 27,25.3 28.5,23.8 39.1,23.8 40.4,22.5 43.5,22.5
PB1: length 31.8
  TOP w0.175: v1(27.75,26.75) 27.75,27.3 27.25,27.8 U1.27 ; U2.19 26.25,32.1 25.4,32.95 v1(25.1,32.95)
  BOTTOM w0.175: v1(25.1,32.95) 25.45,32.95 26.2,32.2 26.2,29.7 27.75,28.15 v1(27.75,26.75) 27.75,25.35 28.9,24.2 39.1,24.2 39.9,25 44.3,25
PB2: length 33.5
  TOP w0.175: v1(28.5,25.85) 28.5,27.25 27.75,28 U1.28 ; v1(26.05,33.45) 26.05,32.89 26.75,32.19 U2.20
  BOTTOM w0.175: v1(26.05,33.45) 26.2,33.3 26.2,32.75 26.75,32.2 26.75,29.95 28.5,28.2 v1(28.5,25.85) 28.5,25.4 29.3,24.6 38.9,24.6 41.9,27.6 44.7,27.6
PB3: length 69.1
  TOP w0.175: U1.55 26.75,42.75 27,43 v1(27,44.35)
  TOP w0.2: v1(27,44.35) 27.95,45.3 36.8,45.3 39.2,47.7 R35.2 ; U2.39 27.75,38.33 v1(27.9,38.17)
  BOTTOM w0.175: 4.8,58.3 6.3,58.3 12.8,64.8 23.9,64.8 27,61.7 v1(27,44.35) 27,42.75 27.9,41.85 v1(27.9,38.17)
PB4: length 41.3
  TOP w0.175: U1.56 v1(26.25,43.45) 26.25,44.85 25.6,45.5 R41.2 ; U2.40 27.25,38.6 27.15,38.5 27.15,37.75 v1(27.85,37.05)
  BOTTOM w0.175: v1(27.85,37.05) 27.19,37.71 27.19,41.71 26.25,42.65 v1(26.25,43.45) 26.25,44.65 15.5,55.4 6.7,55.4
PB5: length 35.9
  TOP w0.175: U2.41 v1(26.75,37.1) ; v1(25.45,44.35) 25.45,43.15 25.75,42.85 U1.57
  BOTTOM w0.175: v1(26.75,37.1) 26.75,41.3 25.45,42.6 v1(25.45,44.35) 25.45,44.65 17.1,53 7,53
PB6: length 31.6
  TOP w0.175: v1(24.7,43.45) 24.7,43.25 25.25,42.7 U1.58 ; v1(26,37.9) 26.25,38.15 U2.42
  BOTTOM w0.175: 7.1,50.2 19.2,50.2 24.7,44.7 v1(24.7,43.45) 24.7,42.45 26,41.15 v1(26,37.9)
PB7: length 35
  TOP w0.175: U1.59 24.75,42.35 23.95,43.15 v1(23.95,44.35) ; U2.43 25.75,38.65 25.25,38.15 25.25,37.25 v1(25.7,36.8)
  BOTTOM w0.175: v1(25.7,36.8) 25.25,37.25 25.25,41 23.95,42.3 v1(23.95,44.35) 23.95,44.75 20.8,47.9 5.7,47.9
PB8: length 33.5
  TOP w0.175: v1(22.45,44.35) 22.45,43.15 23.75,41.85 U1.61 ; v1(24.19,36.95) 24.35,37.11 24.35,38.35 24.75,38.75 U2.45
  BOTTOM w0.175: 4.5,42.9 10.5,42.9 11.95,44.35 v1(22.45,44.35) 22.45,42.1 24.4,40.15 24.4,37.16 v1(24.19,36.95)
PB9: length 29.6
  TOP w0.175: v1(23.6,37.85) 23.6,38.2 24.25,38.85 U2.46 ; v1(21.7,43.45) 21.7,43.3 23.25,41.75 U1.62
  BOTTOM w0.175: 4.8,40.2 10,40.2 13.25,43.45 v1(21.7,43.45) 21.7,42.05 23.6,40.15 v1(23.6,37.85)
PB10: length 29.3
  TOP w0.175: v1(29.25,26.75) 29.25,27.05 28.25,28.05 U1.29 ; v1(27.55,31.96) 27.25,31.66 U2.21
  BOTTOM w0.175: v1(27.55,31.96) 27.55,29.85 29.25,28.15 v1(29.25,26.75) 29.25,25.4 29.65,25 38.7,25 43.9,30.2 44.7,30.2
PB11: length 31.8
  TOP w0.175: v1(30,25.85) 30,27.1 28.75,28.35 U1.30 ; U2.22 27.75,31.15 v1(28.8,32.2)
  BOTTOM w0.175: 44.2,32.7 39.5,32.7 35.9,29.1 31.8,29.1 31,29.9 31,31.5 30.3,32.2 v1(28.8,32.2) 28.8,29.35 30,28.15 v1(30,25.85)
PB12: length 18.4
  TOP w0.175: U2.25 30.48,31.68 30.91,31.25 U1.33
  TOP w0.2: U1.33 v1(31.98,30.54)
  BOTTOM w0.175: 44.6,35.2 41.4,35.2 35.7,29.5 33,29.5 31.98,30.52 v1(31.98,30.54)
PB13: length 23.8
  TOP w0.175: U2.26 29.76,32.75 29.51,32.49 29.51,31.79 31.5,29.8 33.15,29.8 ; 33.15,29.8 33.9,29.8 v1(34.35,30.25) ; 33.15,29.8 33.15,31.25 32.65,31.75 U1.34
  BOTTOM w0.175: v1(34.35,30.25) 35.85,30.25 43.4,37.8 44.6,37.8
PB14: length 30.8
  TOP w0.175: v1(27.05,32.95) 27.33,32.67 28.27,32.67 28.85,33.25 U2.27 ; v1(35.2,31) 34,31 32.75,32.25 U1.35
  BOTTOM w0.175: v1(27.05,32.95) 27.25,32.75 28.3,32.75 28.5,32.95 31.85,32.95 33.8,31 v1(35.2,31) 36,31 43.4,38.4 43.4,39.6 44,40.2 44.8,40.2
PB15: length 29.4
  TOP w0.175: v1(34.35,31.75) 34.15,31.75 33.15,32.75 U1.36 ; U2.28 28.3,33.75 v1(28.05,33.5)
  BOTTOM w0.175: 44.7,42.9 43.8,42.9 43,42.1 43,38.6 36.15,31.75 v1(34.35,31.75) 32.6,33.5 v1(28.05,33.5)
PC0: length 18.9
  TOP w0.175: v1(16.5,35.5) 18.05,35.5 18.3,35.25 U1.8
  BOTTOM w0.175: 6.4,27.5 11.3,27.5 12.3,28.5 12.3,31.6 16.2,35.5 v1(16.5,35.5)
PC1: length 21.7
  TOP w0.175: U1.9 v1(17.5,34.75)
  BOTTOM w0.175: v1(17.5,34.75) 16.15,34.75 12.7,31.3 12.7,28.2 9.5,25 4.2,25
PC2: length 23
  TOP w0.175: U1.10 18.3,34.25 18.05,34 v1(16.5,34)
  BOTTOM w0.175: 4.3,22.5 8.7,22.5 13.1,26.9 13.1,31
  BOTTOM w0.2: v1(16.5,34) 16.1,34 13.1,31
PC3: length 24
  TOP w0.175: U1.11 18.65,33.75 18.15,33.25 v1(17.5,33.25)
  BOTTOM w0.175: 4.2,19.9 6.8,19.9 13.49,26.59 13.49,30.69
  BOTTOM w0.2: 13.49,30.69 16.05,33.25 v1(17.5,33.25)
PC4: length 26.5
  TOP w0.175: U1.24 25.75,27.4 25.5,27.15 v1(25.5,25.9)
  BOTTOM w0.175: v1(25.5,25.9) 25.5,24.9 27.4,23 38.7,23 44.4,17.3 44.6,17.3
PC5: length 23.2
  TOP w0.175: U1.25 v1(26.25,26.75)
  BOTTOM w0.175: 43.4,19.9 42.4,19.9 38.9,23.4 28,23.4 26.25,25.15 v1(26.25,26.75)
PC6: length 21.5
  TOP w0.175: U1.37 33.25,33.25 34,32.5 v1(35.2,32.5)
  BOTTOM w0.175: v1(35.2,32.5) 36.3,32.5 42.6,38.8 42.6,44.6 43.4,45.4 44.4,45.4
PC7: length 23.4
  TOP w0.175: U1.38 33.4,33.75 33.9,33.25 v1(34.35,33.25)
  BOTTOM w0.175: 44.5,47.9 43.3,47.9 42.2,46.8 42.2,39 36.45,33.25 v1(34.35,33.25)
PC8: length 54
  TOP w0.175: U1.39 33.65,34.25 33.9,34 v1(35.15,34) 38,34 39.3,32.7 39.3,25.2 38.2,24.1 26.9,24.1 26,23.2 R23.1
  BOTTOM w0.175: v1(35.15,34) 36.6,34 41.8,39.2 41.8,48.4 43.1,49.7 43.9,50.5 44.5,50.5
PC9: length 56.6
  TOP w0.175: 27.5,23.1 28.1,23.7 38.37,23.7 39.7,25.03 39.7,33 37.95,34.75 v1(34.3,34.75) U1.40
  TOP w0.2: 27.5,23.1 R27.1
  BOTTOM w0.175: 44.7,53 43.9,53 42.7,51.8 42.7,49.9 41.4,48.6 41.4,39.4 36.75,34.75 v1(34.3,34.75)
PC10: length 72.5
  TOP w0.175: U1.51 28.75,41.9 30.05,43.2 v1(30.05,44.35) ; 41.3,43.3 41.3,24.3 39.5,22.5 R28.1
  BOTTOM w0.175: 4.8,68.2 7,68.2 8.8,66.4 24.7,66.4 30.05,61.05 v1(30.05,44.35)
PC11: length 73.2
  TOP w0.175: v1(29.25,43.45) 29.25,43.15 28.25,42.15 U1.52 ; 40.9,43.3 40.9,24.5 38.9,22.5 36.7,22.5 36.5,22.3 R26.1
  BOTTOM w0.175: v1(29.25,43.45) 29.25,61.25 24.5,66 12.1,66 11.4,65.3 5,65.3
PC12: length 79
  TOP w0.175: U1.53 27.75,42.35 28.5,43.1 v1(28.5,44.35) ; R25.1 30.5,23 30.8,23.3 38.53,23.3 40.1,24.87 40.1,43.3
  BOTTOM w0.175: 4.4,63 9.8,63 12.4,65.6 24.3,65.6 28.5,61.4 v1(28.5,44.35)
PC13: length 25.3
  TOP w0.175: 18.8,40.2 20.55,40.2 22.43,38.33 22.43,37.58 22.1,37.25 U2.2 ; 18.8,40.2 18.8,38.8 19.35,38.25 U1.2 ; 18.8,40.2 v1(16.4,40.2)
  BOTTOM w0.175: v1(16.4,40.2) 15.6,40.2 10.6,35.2 4.6,35.2
PD2: length 76.2
  TOP w0.175: R24.1 33.5,22.5 33.9,22.9 38.7,22.9 40.5,24.7 40.5,43.3 ; U1.54 27.25,42.6 27.75,43.1 v1(27.75,43.45)
  BOTTOM w0.175: 4.4,60.5 7.9,60.5 12.6,65.2 24.1,65.2 27.75,61.55 v1(27.75,43.45)
SRST: length 10.6
  TOP w0.175: U6.12 17.35,52.45 17.9,53 17.9,55.2 19.1,56.4 20.6,56.4 21.45,57.25 U3.11
SRST_OE: length 14.6
  TOP w0.175: 18.3,51.8 16.4,51.8 ; 18.3,51.8 18.3,51.2 19,50.5 R39.2 ; 18.3,51.8 18.3,55 19.3,56 20.8,56 21.55,56.75 U3.12
  TOP w0.2: 16.4,51.8 U6.13
TRST: length 4.2
  TOP w0.2: U3.13 22.73,55.23 22.2,54.7 22.2,54 21.95,53.75 20.62,53.75
TRST_OE: length 16.4
  TOP w0.175: U3.15 24.85,56.05 24.6,56.3 21.7,56.3 21,55.6 19.5,55.6 18.7,54.8 18.7,53.1 ; R40.2 20.5,49.6 18.7,51.4 18.7,53.1 ; 20.62,53.1 18.7,53.1
USB_CLK: length 11.9
  TOP w0.175: U5.12 39.15,56.95 37.42,55.23 U3.24
USB_TDI: length 15.9
  TOP w0.175: U3.23 28.85,54.55 29.2,54.2 35.9,54.2 36.4,54.7 37.7,54.7 38.3,55.3 40,55.3 41.1,56.4 U5.9
USB_TDO: length 12.5
  TOP w0.175: R34.1 36.2,53.3 35.7,53.8 29,53.8 28.35,54.45 U3.22
USB_TMS: length 16.1
  TOP w0.175: U3.21 27.85,54.35 28.8,53.4 34.7,53.4 v1(35.2,52.9)
  TOP w0.2: v1(36.8,53.9) 37,54.1 37.9,54.1 38.2,54.4 39.9,54.4 40.45,53.85 U5.5
  BOTTOM w0.2: v1(35.2,52.9) 35.8,52.9 v1(36.8,53.9)
N50123: length 24.6
  TOP w0.175: R13.1 18.49,60.31 19.3,59.5 19.3,58.4 19.6,58.1 20.7,58.1 21,58.4 21,58.9 21.35,59.25 U3.7
  TOP w0.2: U12.4 v1(11.45,61.25) ; U3.7 23.65,59.25 v1(24,59.6)
  BOTTOM w0.2: v1(11.45,61.25) 12,61.8 12,62.4 12.5,62.9 15.7,62.9 19.37,59.23 22.73,59.23 23.1,59.6 v1(24,59.6)
N50127: length 3.8
  TOP w0.2: U3.46 24.85,65.2 C18.1 22.76,65.8 R4.2
N50535: length 1.9
  TOP w0.2: R7.1 27.35,53.56 U3.20
N50793: length 7.5
  TOP w0.2: Y3.1 26.35,70.5 U3.43
N50801: length 9.9
  TOP w0.2: Y3.2 23.46,71.04 25.85,68.65 U3.44
N51029: length 2
  TOP w0.8: L1.1 D2.A
N51243: length 3.3
  TOP w0.5: L1.2 14.62,65.97 14.1,66.5 J1.1
N51319: length 2.3
  TOP w0.2: U3.5 21.05,60.25 20.8,60.5 R13.2
N51343: length 17.8
  TOP w0.2: v1(24,58.3) 23.55,58.75 U3.8 ; U12.6 v1(13.35,61.26)
  BOTTOM w0.2: v1(13.35,61.26) 13.14,61.26 12.5,61.9 12.5,62.2 12.8,62.5 15.5,62.5 19.17,58.83 22.67,58.83 23.2,58.3 v1(24,58.3)
N51347: length 4.2
  TOP w0.175: U3.4 21.55,60.75 20.3,62 R6.1
  TOP w0.2: R5.2 R6.1
N51363: length 2.6
  TOP w0.2: U3.6 20.95,59.75 C19.1
N70187: length 6.3
  TOP w0.2: R15.2 28.1,8.3 28.4,8 U10.7
N70219: length 10
  TOP w0.2: R17.2 30.23,9.8 30.6,9.43 U10.5
N70227: length 16
  TOP w0.2: R18.2 24.91,12.9 33.5,12.9 33.9,12.5 U10.2
N70603: length 3.7
  TOP w0.2: R19.2 27,6.8 27.3,6.5 U10.8
N14914218: length 13.7
  TOP w0.2: R16.2 32.5,11.3 32.8,11 U10.3
N14919452: length 2.8
  TOP w0.2: U5.3 39.15,49.96 R35.1
N14919456: length 3.2
  TOP w0.2: U5.6 41.1,51.8 42.2,50.7 R36.1
N14919460: length 8.8
  TOP w0.2: U5.8 v1(41.75,56) ; v1(40.7,50.9) R37.1
  BOTTOM w0.175: v1(41.75,56) 41.75,54.95 40.7,53.9 v1(40.7,50.9)
N14919464: length 9.3
  TOP w0.2: v1(37.7,50.9) R38.1 ; U5.11 v1(39.8,56.3)
  BOTTOM w0.175: v1(39.8,56.3) 39.8,55.7 38.4,54.3 38.4,51.6 v1(37.7,50.9)
N14919761: length 18.9
  TOP w0.2: U10.1 35,13.9 34.6,14.3 R20.2
N14928580: length 5.3
  TOP w0.2: R42.1 13.3,50.19 13.3,52.4 14,53.1 U6.11
N14948554: length 8.1
  TOP w0.2: U11.1 41.75,65.35 41.3,65.8 40.1,65.8 39.8,66.1 37.2,66.1 36.8,66.5 J2.2
N14948558: length 8.3
  TOP w0.2: J2.3 36,66.5 36.9,65.6 39.6,65.6 39.88,65.32 39.88,65.08 39.7,64.9 39.22,64.9 38.98,64.66 38.98,64.38 39.16,64.2 39.55,64.2 U11.3
N14952468: length 1.8
  TOP w0.2: Q1.2 36.73,61.58 37,61.3 37.79,61.3 R46.1
N14953185: length 9
  TOP w0.2: R44.2 29.11,65.79 29.8,65.1 Q2.3 R45.1 34.25,64.94 Q1.1
N14959571: length 3.5
  TOP w0.2: U12.3 11.45,65.45 12.5,66.5 J1.3
N14961045: length 3.5
  TOP w0.2: U12.1 13.35,65.15 12.74,65.76 12.74,66.04 13.3,66.6 J1.2
N14964930: length 3.8
  TOP w0.175: U1.31 29.25,28.35 29.8,27.8 30.4,27.8 31.3,26.9 C27.1
N14964937: length 5.2
  TOP w0.2: R48.1 35.59,40.7 C28.1 33.2,39.8 33.2,38.9 32.55,38.25 U1.47

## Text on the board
DIMENSION: FIGURE | SIZE | 0.508 | 0.8 | 0.8999 | 0.9144 | 1.0 | 2.4 | DRILL CHART: TOP to BOTTOM | ALL UNITS ARE IN MILLIMETERS | PLATED | QTY | 121 | 14 | 200 | 2 | 4
